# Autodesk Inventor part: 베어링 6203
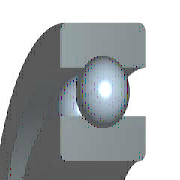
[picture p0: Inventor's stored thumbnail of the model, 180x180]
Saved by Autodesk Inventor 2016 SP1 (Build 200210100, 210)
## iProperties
IsCustomPart: 0
Created: 2016-04
Part Number: 베어링 6203
Material: 알루미늄 6061
Description: 깊은 그루브 볼 베어링
Document SubType Name: Modeling
Standard: KS B 2023
Designer: mdu
Standards Organization: KS
Language: ko-KR
Size Designation: 6203 - 17 x 40 x 12
Categories: <MemberInstance><Categories><Category DisplayName="샤프트 부품" InternalName="7f7aeb1f-a693-4053-b835-cee3144e0d98" Mnemonic="SHFT"><Category DisplayName="베어링" Inter
Density: 2.71 g/cm^3
Mass: 22.4044 g
Surface Area: 64.3582 cm^2
Volume: 8.26729 cm^3
Appearance: 알루미늄 - 평지
Author: mdu
Revision Number: 1
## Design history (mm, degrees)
sketch "스케치" dims "d0" = 5.98 (= -0.26 x WD + 0.26 x BD)
  geometry: L1 (3.01, 14.25)-(8.99, 14.25); L2 (6, 14.25)-(6, 11.26); L3 (6, 14.25)-(6, 17.24); L4 (3.778, 12.249)-(0, 12.249); L5 (0, 8.5)-(12, 8.5); L6 (3.778, 16.251)-(0, 16.251); L7 (0, 20)-(12, 20); L8 (12, 8.5)-(12, 12.249); L9 (8.222, 12.249)-(12, 12.249); L10 (8.222, 16.251)-(12, 16.251); L11 (12, 20)-(12, 16.251); L12 (-1.4, 0)-(8.4, 0) reference; L13 (0, -0.3)-(0, 5.3) reference
  constraints: 22 end point, 4 point on line, 2 collinear, 2 perpendicular, 2 symmetric about line, 1 midpoint, 1 parallel, 14 other
  dimensions: "d9" = 17 diameter of L5 L12 (= WD); "d11" = 40 diameter of L7 L12 (= BD); "d12" = 12 distance between parallel lines of L8 L13 (= KB); "d13" = 24.498 diameter of L9 L12 (= 0.326 x BD + 0.674 x WD)
revolve "본체" stored, may be unused: angle "d6" = 90 deg
revolve "볼" stored, may be unused: angle "d7" = 90 deg
pattern_circular "IDS_ARRAYBALL[SIMPL:T]" dims angle "d3" = 360 deg
body "Solid1"
fillet "모깎기1" dims "d1" = 0.6 (= KRS)
other parameters: "WD" = 17 [user parameter; used in 5 equation terms], "BD" = 40 [user parameter; used in 5 equation terms], "KB" = 12 [user parameter; used in 1 equation term], "KRS" = 0.6 [user parameter; used in 1 equation term], "d4" = 0, "d5" = 0, "d8" = 0, "d14" = 0, "d15" = 0, "BBA" = 0 [user parameter], "BC0" = 4750000 [user parameter], "BC" = 9560000 [user parameter], "WR" = 8.5 (= 0.5 x WD) [user parameter]
